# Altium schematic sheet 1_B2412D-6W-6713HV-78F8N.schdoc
size 289 x 200 mm; Name: default297x210; Symbol: default297x210; Device: default297x210; Date: 2025.06.26; Rev: V1.1; Size: "A4"; Id: /; File: B2412D-6W-6713HV-78F8N; Sheet: /; @Page No: 1; @Page Count: 1; @Schematic Name: B2412D-6W-6713HV-78F8N; @Project Name: 全桥隔离电源-B2412D-6W-6713HV-78F8N; @Board Name: B2412D-6W-6713HV-78F8N; @Update Date: 2025-06-26; @Create Time: 15:00:27; @Update Time: 15:00:27; @Page Name: B2412D-6W-6713HV-78F8N; @Create Date: 2025-06-26
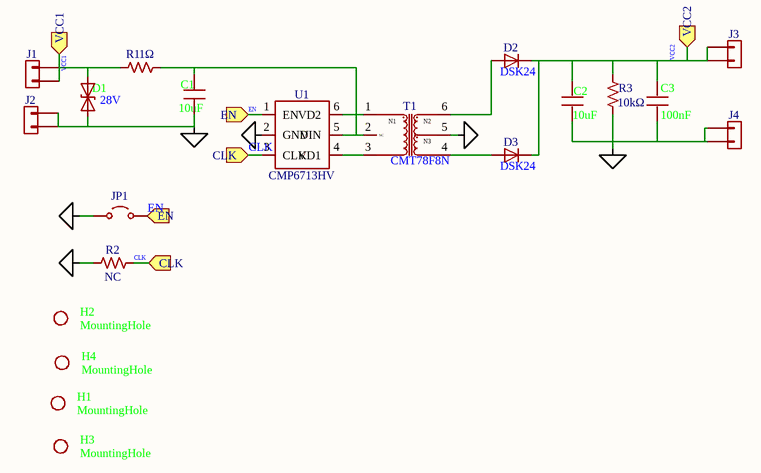
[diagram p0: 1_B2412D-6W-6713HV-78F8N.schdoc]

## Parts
C1  10uF  [C0805]
C2  10uF  [C0805]
C3  100nF  [C0603]
D1  Reverse Stand-Off Voltage (Vrwm): 28V  [SOD-123FL_L2.8-W1.8-LS3.7-BI]  (hidden comment: SMF28CA)
D2  DSK24  [SOD-123_L2.8-W1.8-LS3.7-RD]
D3  DSK24  [SOD-123_L2.8-W1.8-LS3.7-RD]
H1  value MountingHole  [MountingHole:MountingHole_3.2mm_M3]  (hidden comment: Mechanical_MountingHole)
H2  value MountingHole  [MountingHole:MountingHole_3.2mm_M3]  (hidden comment: Mechanical_MountingHole)
H3  value MountingHole  [MountingHole:MountingHole_3.2mm_M3]  (hidden comment: Mechanical_MountingHole)
H4  value MountingHole  [MountingHole:MountingHole_3.2mm_M3]  (hidden comment: Mechanical_MountingHole)
J1  Connector_Generic_Conn_01x02  [Connector_PinHeader_2.54mm:PinHeader_1x02_P2.54mm_Vertical]  (value not drawn)
J2  Connector_Generic_Conn_01x02  [Connector_PinHeader_2.54mm:PinHeader_1x02_P2.54mm_Vertical]  (value not drawn)
J3  Connector_Generic_Conn_01x02  [Connector_PinHeader_2.54mm:PinHeader_1x02_P2.54mm_Vertical]  (value not drawn)
J4  Connector_Generic_Conn_01x02  [Connector_PinHeader_2.54mm:PinHeader_1x02_P2.54mm_Vertical]  (value not drawn)
JP1  Jumper_Jumper_2_Open  [Connector_PinHeader_2.54mm:PinHeader_1x02_P2.54mm_Vertical]  (value not drawn)
R1  1Ω  [R0603]
R2  NC  [R0603]
R3  10kΩ  [R0603]
T1  CMT78F8N  [XFMR-SMD_CMT78GFN1]
U1  CMP6713HV  [Package_TO_SOT_SMD:TSOT-23-6]

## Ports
CLK (in), EN (in), VCC1 (in), VCC2 (in)

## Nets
GND1: C1.1 D1.2 J2.1 J2.2 JP1.1 R2.1 U1.2(GND)
GND2: C2.1 C3.1 J4.1 J4.2 R3.2 T1.5
CLK: R2.2 U1.3(CLK) ; port CLK
EN: JP1.2 U1.1(EN) ; port EN
VCC1: D1.1 J1.1 J1.2 R1.1 ; port VCC1
VCC2: C2.2 C3.2 D2.1 D3.1 J3.1 J3.2 R3.1 ; port VCC2
NetC1_2: C1.2 R1.2 T1.2 U1.5(VIN)
NetD2_2: D2.2 T1.6
NetD3_2: D3.2 T1.4
NetT1_1: T1.1 U1.6(VD2)
NetT1_3: T1.3 U1.4(VD1)

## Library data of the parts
C1 = CGA0805X5R106K350MT: Manufacturer: HRE(芯声); Symbol: My_Library_C; Add into BOM: yes; Tolerance: ±10%; Voltage Rating: 35V; Temperature Coefficient: X5R
C2 = CC0805KKX5R8BB106_C89831: Manufacturer: YAGEO(国巨); Symbol: My_Library_C; Add into BOM: yes; Tolerance: ±10%; Voltage Rated: 25V; Temperature Coefficient: X5R
C3 = CC0603KRX7R9BB104: Manufacturer: YAGEO(国巨); Symbol: My_Library_C; Add into BOM: yes; Tolerance: ±10%; Voltage Rating: 50V; Temperature Coefficient: X7R
D1 = SMF28CA_C364280: Manufacturer: MDD(辰达半导体); Symbol: Diode_SMAJ30CA; Add into BOM: yes; polarity: 双向; Maximum Clamping Voltage: 45.4V; Peak Pulse Current (Ipp): 4.4A; Peak Pulse Power Dissipation (Ppp): 200W; Breakdown Voltage: 34.4V; Reverse Leakage Current (Ir): 1uA; Type: TVS
D2 D3 = DSK24 K24: Manufacturer: MDD(辰达半导体); Symbol: My_Library_D; Add into BOM: yes; Diode Configuration: 独立式; Forward Voltage (Vf@If): 550mV@2A; Reverse Voltage (Vr): 40V; Rectified Current: 2A; Reverse Leakage Current (Ir): 500uA@40V
H1-H4 = Mechanical_MountingHole: Users: REF**; ki_fp_filters: MountingHole*; Add into BOM: yes
J1-J4 = Connector_Generic_Conn_01x02: Users: REF**; ki_fp_filters: Jumper* TestPoint*2Pads* TestPoint*Bridge*; Add into BOM: yes
JP1 = Jumper_Jumper_2_Open: Add into BOM: yes
R1 = RC0603FR-071RL: Manufacturer: YAGEO(国巨); Symbol: My_Library_R; Add into BOM: yes; Tolerance: ±1%; Power(Watts): 100mW; Overload Voltage (Max): 75V; Temperature Coefficient: ±200ppm/℃
R2 = RC0603FR-0715KL: Symbol: My_Library_R; Add into BOM: yes; Tolerance: ±1%
R3 = RC0603FR-0710KL: Manufacturer: YAGEO(国巨); Symbol: My_Library_R; Add into BOM: yes; Tolerance: ±1%; Power(Watts): 100mW; Overload Voltage (Max): 75V; Temperature Coefficient: ±100ppm/℃
T1 = CMT78F8N: Manufacturer: coileasy(线易); Symbol: My_Library_VPT85BB-02A; Add into BOM: yes
U1 = CMP6713HV: Manufacturer: coileasy(线易); Symbol: MYLibrary_CMP6713RE/HV; Add into BOM: yes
